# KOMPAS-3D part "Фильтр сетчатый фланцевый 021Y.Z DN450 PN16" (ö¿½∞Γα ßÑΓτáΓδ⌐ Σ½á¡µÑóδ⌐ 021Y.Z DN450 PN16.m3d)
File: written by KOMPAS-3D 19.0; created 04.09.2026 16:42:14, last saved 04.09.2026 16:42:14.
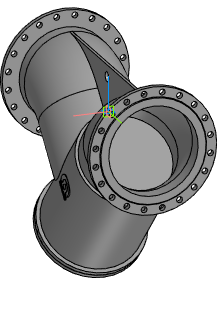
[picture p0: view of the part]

Document properties: Автор: Энергия; Полное имя файла: Z:\3.Личные\sachek\Dendor\_3D для проектировщиков\8.1 Фильтр сетчатый 021Y.Z\021Y.Z_STP\Фильтр сетчатый фланцевый 021Y.Z DN450 PN16.m3d

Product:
- Part/product: Фильтр сетчатый фланцевый 021Y.Z DN450 PN16

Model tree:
1. Операция без истории:1  (labels: Фильтр сетчатый фланцевый 021Y.Z DN450 PN16)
